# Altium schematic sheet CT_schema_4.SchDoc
size 276 x 169 mm
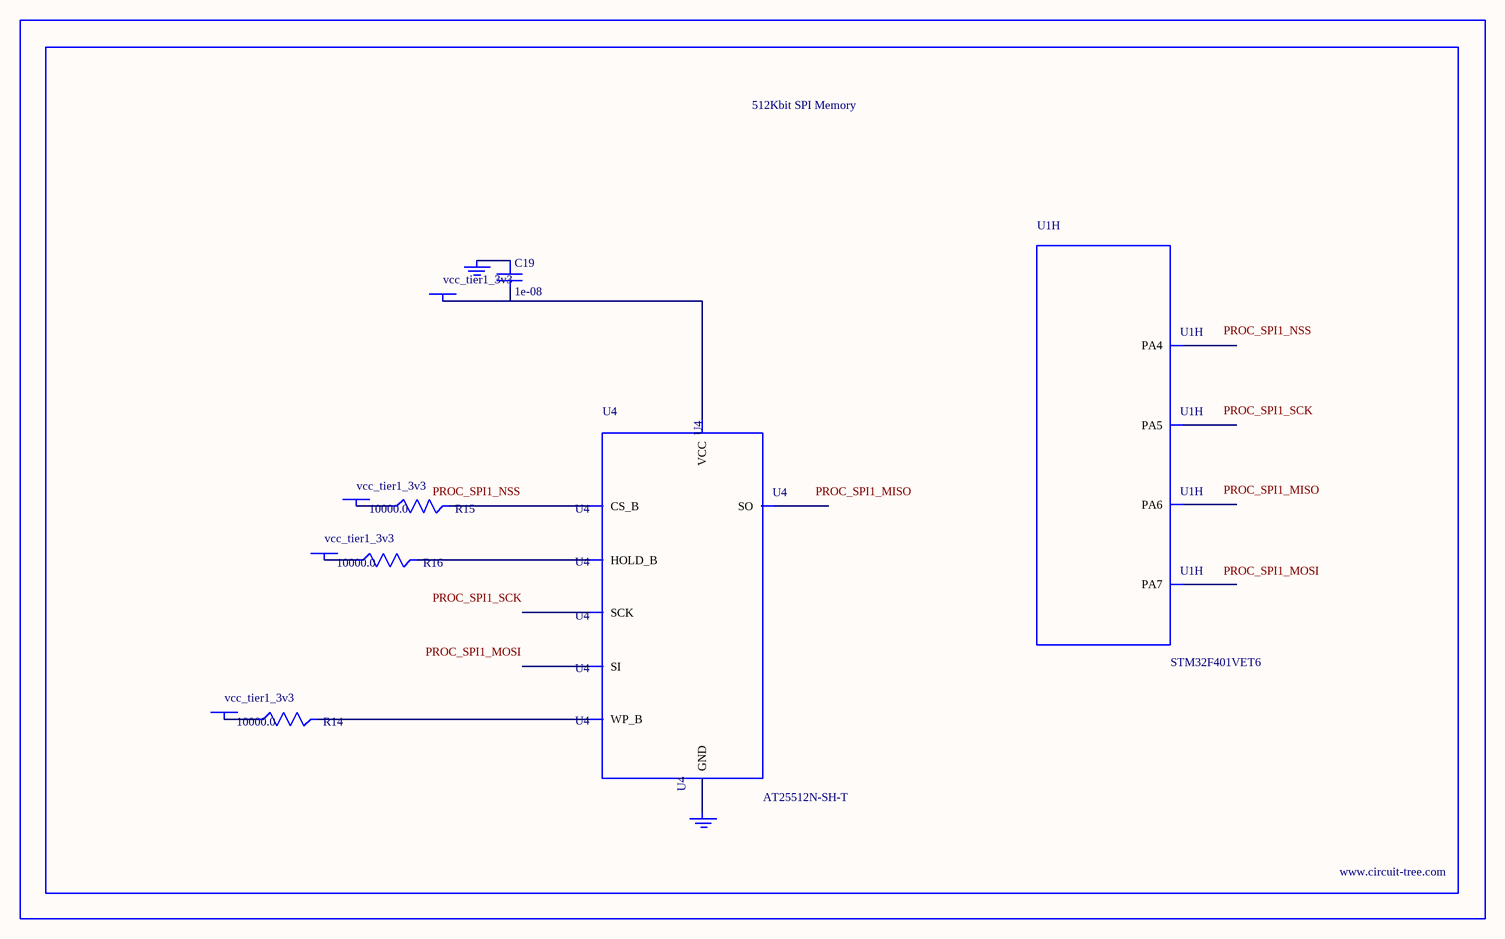
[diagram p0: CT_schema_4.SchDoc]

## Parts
BORDER3  (no value)
C19  1e-08  [C0402]
GND_INSTANCE_3_0  (no value)
GND_INSTANCE_3_1  (no value)
POWER_INSTANCE_3_0  vcc_tier1_3v3
POWER_INSTANCE_3_1  vcc_tier1_3v3
POWER_INSTANCE_3_2  vcc_tier1_3v3
POWER_INSTANCE_3_3  vcc_tier1_3v3
R14  10000.0  [R0603]
R15  10000.0  [R0603]
R16  10000.0  [R0603]
U1  STM32F401VET6  [LQFP100]  (part H of 10)
U4  AT25512N-SH-T  [SOIC-8]

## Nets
NetC19_1: C19.1 GND_INSTANCE_3_0.0(GND)
NetC19_2: C19.2 POWER_INSTANCE_3_3.0(PWR) U4.8(VCC)
NetGND_INSTANCE_3_1_0: GND_INSTANCE_3_1.0(GND) U4.4(GND)
NetPOWER_INSTANCE_3_0_0: POWER_INSTANCE_3_0.0(PWR) R15.1
NetPOWER_INSTANCE_3_1_0: POWER_INSTANCE_3_1.0(PWR) R14.1
NetPOWER_INSTANCE_3_2_0: POWER_INSTANCE_3_2.0(PWR) R16.1
NetR14_2: R14.2 U4.3(WP_B)
NetR15_2: R15.2 U4.1(CS_B)
NetR16_2: R16.2 U4.7(HOLD_B)

Not connected (* = marked no-connect by the designer): U1 29(PA4) 30(PA5) 31(PA6) 32(PA7); U4 2(SO) 5(SI) 6(SCK)

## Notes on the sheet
- Labels drawn without touching a wire or pin: PROC_SPI1_MISO, PROC_SPI1_MOSI, PROC_SPI1_NSS, PROC_SPI1_SCK

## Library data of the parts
BORDER3 = BORDER_PAGE3
C19 = C0402C103K3RAC
GND_INSTANCE_3_0 GND_INSTANCE_3_1 = GND
POWER_INSTANCE_3_0-POWER_INSTANCE_3_3 = PWR
R14-R16 = RC0603JR-0710KL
